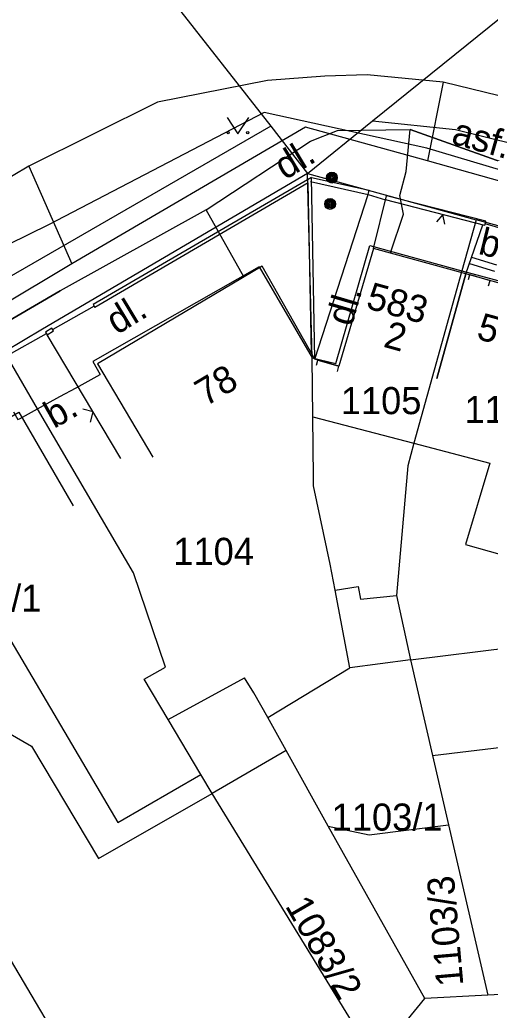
# Model space of a CAD drawing. Extents: x -601580 to 4, y -1204314 to 4.
# Drawn here: x -599937.98 to -599916.3, y -1203331.33 to -1203285.67 of the extents above; entities that cross this region are included whole.
import ezdxf

# ---------------------------------------------------------------- set-up
doc = ezdxf.new("R2010")
doc.units = 0
for name, color, linetype in [('00-KN-HRANICE PARCEL', 7, 'Continuous'), ('00-KN-PARC. CISLA', 7, 'Continuous'), ('00-KN-VNITRNI KRESBA', 7, 'Continuous'), ('00-POLOHOPIS', 7, 'Continuous'), ('00-SITE KOM. KABEL', 7, 'Continuous'), ('Vrstva 25', 7, 'Continuous'), ('Vrstva 36', 7, 'Continuous'), ('Vrstva 6', 7, 'Continuous')]:
    doc.layers.add(name, color=color, linetype=linetype)

# ---------------------------------------------------------------- blocks, each defined once
blk = doc.blocks.new('6.01A_38')
at = {"layer": 'Vrstva 25'}
for radius in [0.25, 0.2, 0.15, 0.1, 0.05]:
    blk.add_circle((0, 0), radius, dxfattribs=at)
blk = doc.blocks.new('6.01A_40')
at = {"layer": 'Vrstva 25'}
for radius in [0.25, 0.2, 0.15, 0.1, 0.05]:
    blk.add_circle((0, 0), radius, dxfattribs=at)
blk = doc.blocks.new('3.14_460')
at = {"layer": 'Vrstva 36'}
blk.add_lwpolyline([(-0.5, 0.75), (0, 0), (0.5, 0.75)], dxfattribs=at)
for centre in [(-0.45, 0.05), (0.449, 0.05)]:
    blk.add_circle(centre, 0.05, dxfattribs=at)
blk = doc.blocks.new('VCHOD_1348')
at = {"layer": 'Vrstva 6'}
blk.add_line((0, 0.25), (0, 0), dxfattribs=at)
blk = doc.blocks.new('VCHOD_1350')
at = {"layer": 'Vrstva 6'}
blk.add_line((0, 0.25), (0, 0), dxfattribs=at)
blk = doc.blocks.new('VCHOD_1352')
at = {"layer": 'Vrstva 6'}
blk.add_line((0, 0.25), (0, 0), dxfattribs=at)
blk = doc.blocks.new('VCHOD_1354')
at = {"layer": 'Vrstva 6'}
blk.add_line((0, 0.25), (0, 0), dxfattribs=at)

msp = doc.modelspace()

# ---------------------------------------------------------------- linework, layer by layer
at = {"layer": '00-KN-HRANICE PARCEL'}
for p, q in [((-599937.93, -1203275.87), (-599926.41, -1203290.58)), ((-599924.72, -1203292.75), (-599921.72, -1203290.33)), ((-599926.41, -1203290.58), (-599924.72, -1203292.75)), ((-599924.72, -1203292.75), (-599936.93, -1203299.93)), ((-599924.72, -1203292.75), (-599916.95, -1203294.89)), ((-599911.01, -1203296.53), (-599916.95, -1203294.89)), ((-599936.93, -1203299.93), (-599938.69, -1203300.98)), ((-599919.97, -1203315.18), (-599922.77, -1203315.55)), ((-599925.71, -1203319.35), (-599929.12, -1203321.33)), ((-599923.76, -1203322.84), (-599925.71, -1203319.35)), ((-599922.09, -1203332.8), (-599929.12, -1203321.33)), ((-599918.22, -1203322.78), (-599916.41, -1203330.63)), ((-599919.31, -1203330.79), (-599923.76, -1203322.84)), ((-599932.66, -1203338.67), (-599941.47, -1203323.84)), ((-599913.23, -1203330.46), (-599916.41, -1203330.63)), ((-599920.12, -1203331.78), (-599919.31, -1203330.79)), ((-599916.41, -1203330.63), (-599919.31, -1203330.79))]:
    msp.add_line(p, q, dxfattribs=at)
for points in [[(-599921.72, -1203290.33), (-599909.86, -1203280.75), (-599905.6, -1203277.3)], [(-599921.72, -1203290.33), (-599917.89, -1203290.73), (-599893.03, -1203296.87), (-599826.78, -1203316.44), (-599809.21, -1203321.87), (-599773.41, -1203332.68), (-599750.39, -1203339.7), (-599709.77, -1203354.1), (-599677.07, -1203366.64), (-599676.9, -1203368.84), (-599676.98, -1203369.55)], [(-599926.41, -1203290.58), (-599968.42, -1203314.8), (-600008.7, -1203338.17), (-600030.28, -1203350.89), (-600042.85, -1203358.3), (-600043.08, -1203360.17), (-600042.39, -1203361.48)], [(-599922.77, -1203315.55), (-599923.45, -1203311.96), (-599923.68, -1203310.76), (-599924.45, -1203307.15), (-599924.45, -1203306.76), (-599924.47, -1203303.97), (-599924.5, -1203301.25), (-599924.72, -1203292.75)], [(-599916.95, -1203294.89), (-599917.6, -1203297.24), (-599919.82, -1203305.19), (-599920.1, -1203306.23), (-599920.62, -1203312.21), (-599919.97, -1203315.18)], [(-599932.25, -1203316.06), (-599931.27, -1203315.52), (-599932.74, -1203311.17), (-599937.16, -1203303.6), (-599938.69, -1203300.98)], [(-599946.73, -1203308.74), (-599942.12, -1203316.47), (-599937.44, -1203319.15), (-599934.36, -1203324.33), (-599929.12, -1203321.33)], [(-599919.97, -1203315.18), (-599918.96, -1203319.59), (-599918.22, -1203322.78)], [(-599925.71, -1203319.35), (-599926.55, -1203317.84), (-599922.77, -1203315.55)], [(-599929.12, -1203321.33), (-599929.64, -1203320.46), (-599931.14, -1203317.93), (-599932.25, -1203316.06)], [(-599923.76, -1203322.84), (-599921.87, -1203323.25), (-599918.22, -1203322.78)]]:
    msp.add_lwpolyline(points, dxfattribs=at)
at = {"layer": '00-KN-VNITRNI KRESBA'}
for p, q in [((-599923.41, -1203301.51), (-599921.85, -1203296.08)), ((-599921.85, -1203296.08), (-599917.6, -1203297.24)), ((-599926.95, -1203297.06), (-599934.62, -1203301.43)), ((-599926.95, -1203297.06), (-599924.5, -1203301.25)), ((-599917.6, -1203297.24), (-599911.68, -1203298.86)), ((-599924.5, -1203301.25), (-599923.41, -1203301.51)), ((-599934.62, -1203301.43), (-599934.28, -1203302.02)), ((-599935.38, -1203302.63), (-599934.28, -1203302.02)), ((-599936.13, -1203303.04), (-599935.38, -1203302.63)), ((-599937.16, -1203303.6), (-599936.13, -1203303.04)), ((-599924.47, -1203303.97), (-599919.82, -1203305.19)), ((-599919.82, -1203305.19), (-599916.32, -1203306.11)), ((-599916.32, -1203306.11), (-599917.44, -1203309.86)), ((-599917.44, -1203309.86), (-599915.06, -1203310.53)), ((-599923.45, -1203311.96), (-599922.39, -1203311.8)), ((-599922.39, -1203311.8), (-599922.28, -1203312.38)), ((-599922.28, -1203312.38), (-599920.62, -1203312.21)), ((-599919.97, -1203315.18), (-599915.1, -1203314.57)), ((-599931.14, -1203317.93), (-599927.62, -1203316.01)), ((-599918.96, -1203319.59), (-599914.65, -1203319.07)), ((-599933.46, -1203322.68), (-599929.64, -1203320.46))]:
    msp.add_line(p, q, dxfattribs=at)
for points in [[(-599938.27, -1203303.75), (-599938.07, -1203304.1), (-599937.99, -1203304.06), (-599937.16, -1203303.6)], [(-599942.12, -1203316.47), (-599938.39, -1203314.3), (-599933.46, -1203322.68)], [(-599926.55, -1203317.84), (-599927.2, -1203316.7), (-599927.62, -1203316.01)]]:
    msp.add_lwpolyline(points, dxfattribs=at)
at = {"layer": '00-POLOHOPIS'}
for p, q in [((-599926.57, -1203288.467), (-599931.632, -1203289.463)), ((-599923.925, -1203288.271), (-599926.57, -1203288.467)), ((-599921.962, -1203288.213), (-599923.925, -1203288.271)), ((-599918.473, -1203288.542), (-599921.962, -1203288.213)), ((-599918.473, -1203288.542), (-599919.188, -1203292.175)), ((-599895.945, -1203294.063), (-599918.473, -1203288.542)), ((-599931.632, -1203289.463), (-599937.566, -1203292.424)), ((-599924.815, -1203290.623), (-599935.579, -1203296.925)), ((-599919.188, -1203292.175), (-599924.815, -1203290.623)), ((-599915.131, -1203293.321), (-599919.188, -1203292.175)), ((-599937.566, -1203292.424), (-599955.672, -1203303.097)), ((-599937.566, -1203292.424), (-599935.579, -1203296.925)), ((-599921.922, -1203293.725), (-599921.878, -1203293.53)), ((-599924.383, -1203301.316), (-599921.922, -1203293.725)), ((-599921.922, -1203293.725), (-599921.126, -1203293.973)), ((-599921.679, -1203296.21), (-599921.076, -1203293.779)), ((-599921.126, -1203293.973), (-599921.076, -1203293.779)), ((-599916.5, -1203294.959), (-599921.076, -1203293.779)), ((-599917.427, -1203297.387), (-599916.641, -1203295.129)), ((-599916.55, -1203295.153), (-599916.5, -1203294.959)), ((-599915.684, -1203295.316), (-599916.528, -1203295.07)), ((-599917.16, -1203296.62), (-599916.011, -1203296.968)), ((-599935.579, -1203296.925), (-599940.573, -1203299.892)), ((-599917.246, -1203296.907), (-599916.097, -1203297.255)), ((-599917.232, -1203297.41), (-599916.303, -1203297.695)), ((-599934.557, -1203298.866), (-599936.463, -1203299.943)), ((-599934.598, -1203298.796), (-599934.522, -1203298.926)), ((-599936.501, -1203299.882), (-599936.797, -1203300.067)), ((-599936.422, -1203300.009), (-599936.501, -1203299.882)), ((-599938.604, -1203301.173), (-599936.757, -1203300.131)), ((-599936.797, -1203300.067), (-599936.718, -1203300.194)), ((-599936.718, -1203300.194), (-599936.422, -1203300.009)), ((-599933.318, -1203305.891), (-599936.718, -1203300.194)), ((-599924.239, -1203301.358), (-599923.268, -1203301.642))]:
    msp.add_line(p, q, dxfattribs=at)
for points in [[(-599924.383, -1203301.316), (-599924.538, -1203292.935), (-599934.598, -1203298.796)], [(-599924.538, -1203292.935), (-599921.878, -1203293.53)], [(-599924.538, -1203301.042), (-599924.683, -1203293.193), (-599934.522, -1203298.926)], [(-599924.582, -1203293.13), (-599921.922, -1203293.725)], [(-599916.55, -1203295.153), (-599921.126, -1203293.973)], [(-599918.393, -1203295.09), (-599918.486, -1203294.653), (-599918.78, -1203294.991)], [(-599918.761, -1203302.206), (-599917.427, -1203297.387), (-599921.679, -1203296.21), (-599923.268, -1203301.642)], [(-599923.268, -1203301.642), (-599924.383, -1203301.316), (-599926.806, -1203297.028), (-599934.398, -1203301.527), (-599931.849, -1203305.828)], [(-599912.776, -1203303.868), (-599911.456, -1203299.045), (-599917.427, -1203297.387), (-599918.761, -1203302.206)], [(-599933.318, -1203305.891), (-599936.718, -1203300.194)], [(-599934.72, -1203304.224), (-599934.599, -1203303.744), (-599935.079, -1203303.623)], [(-599944.115, -1203313.113), (-599946.615, -1203308.783), (-599943.438, -1203306.949), (-599943.603, -1203306.675), (-599941.386, -1203305.34), (-599941.221, -1203305.614), (-599938.033, -1203303.757), (-599935.516, -1203308.077)]]:
    msp.add_lwpolyline(points, dxfattribs=at)
at = {"layer": '00-SITE KOM. KABEL'}
for points in [[(-599885.06, -1203301.1), (-599893.14, -1203298.94), (-599902.85, -1203296.25), (-599915.04, -1203292.84), (-599919.22, -1203291.59), (-599926.71, -1203289.94), (-599936.66, -1203295.12), (-599941.33, -1203297.41), (-599946.06, -1203299.64), (-599947.01, -1203298.35), (-599951.14, -1203292.02), (-599951.96, -1203290.14), (-599948.22, -1203287.12), (-599943.4, -1203283.9), (-599942.04, -1203281.57)], [(-599929.39, -1203294.43), (-599924.58, -1203291.27), (-599923.33, -1203290.78)], [(-599923.33, -1203290.78), (-599919.99, -1203290.73)], [(-599920.9, -1203296.41), (-599920.29, -1203294.63), (-599920.47, -1203293.77), (-599920.17, -1203292.66), (-599919.99, -1203290.73)], [(-599919.99, -1203290.73), (-599913.82, -1203292.93)], [(-599913.82, -1203292.93), (-599919.99, -1203290.73)], [(-599920.47, -1203293.77), (-599920.17, -1203292.66)], [(-599929.39, -1203294.43), (-599936.12, -1203298.16), (-599940.32, -1203300.61), (-599941.06, -1203301.14)], [(-599927.66, -1203297.52), (-599929.39, -1203294.43)], [(-599940.32, -1203300.61), (-599936.12, -1203298.16)]]:
    msp.add_lwpolyline(points, dxfattribs=at)

# ---------------------------------------------------------------- block references
at = {"layer": '00-POLOHOPIS'}
msp.add_blockref('3.14_460', (-599927.924, -1203290.921), dxfattribs=at)
at = {"layer": '00-POLOHOPIS', "rotation": -90.00000000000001}
for name, p in [('6.01A_40', (-599923.595, -1203292.944)), ('6.01A_38', (-599923.678, -1203294.16))]:
    msp.add_blockref(name, p, dxfattribs=at)
at = {"layer": '00-POLOHOPIS'}
for name, p, xscale, yscale, rotation in [('VCHOD_1348', (-599917.232, -1203297.41), 1.00000014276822, 1.00000014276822, 162.9448199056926), ('VCHOD_1350', (-599916.303, -1203297.695), 1.00000014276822, 1.00000014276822, 162.9448199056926), ('VCHOD_1352', (-599924.239, -1203301.358), 1.00000028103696, 1.0000002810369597, 163.6968397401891), ('VCHOD_1354', (-599923.268, -1203301.642), 1.00000028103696, 1.0000002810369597, 163.6968397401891)]:
    msp.add_blockref(name, p, dxfattribs=dict(at, xscale=xscale, yscale=yscale, rotation=rotation))

# ---------------------------------------------------------------- texts
at = {"layer": '00-KN-PARC. CISLA'}
for s, p in [('1105', (-599923.187, -1203303.85)), ('1101', (-599917.484, -1203304.26)), ('1104', (-599930.907, -1203310.8)), ('1082/1', (-599942.095, -1203312.96)), ('1103/1', (-599923.607, -1203323.05))]:
    msp.add_text(s, height=1.25, dxfattribs=at).set_placement(p)
for s, rotation, p in [('1103/3', 95, (-599917.531, -1203330.176)), ('1083/2', 300, (-599925.775, -1203326.519))]:
    msp.add_text(s, height=1.25, rotation=rotation, dxfattribs=at).set_placement(p)
at = {"layer": '00-POLOHOPIS'}
for s, rotation, p in [('asf.', 344.2264, (-599918.138, -1203291.361)), ('dl.', 31.1266, (-599925.76, -1203293.077)), ('b.', 346.3484, (-599916.894, -1203296.454)), ('583', 344.5273, (-599922.077, -1203298.953)), ('dl.', 31.1266, (-599933.516, -1203300.213)), ('dl.', 73.6944, (-599922.685, -1203299.846)), ('583', 344.4813, (-599916.98, -1203300.365)), ('2', 344.5273, (-599921.268, -1203300.734)), ('78', 30.6509, (-599929.423, -1203303.518)), ('b.', 29.4299, (-599936.41, -1203304.536))]:
    msp.add_text(s, height=1.25, rotation=rotation, dxfattribs=at).set_placement(p)

doc.saveas('drawing.dxf')
